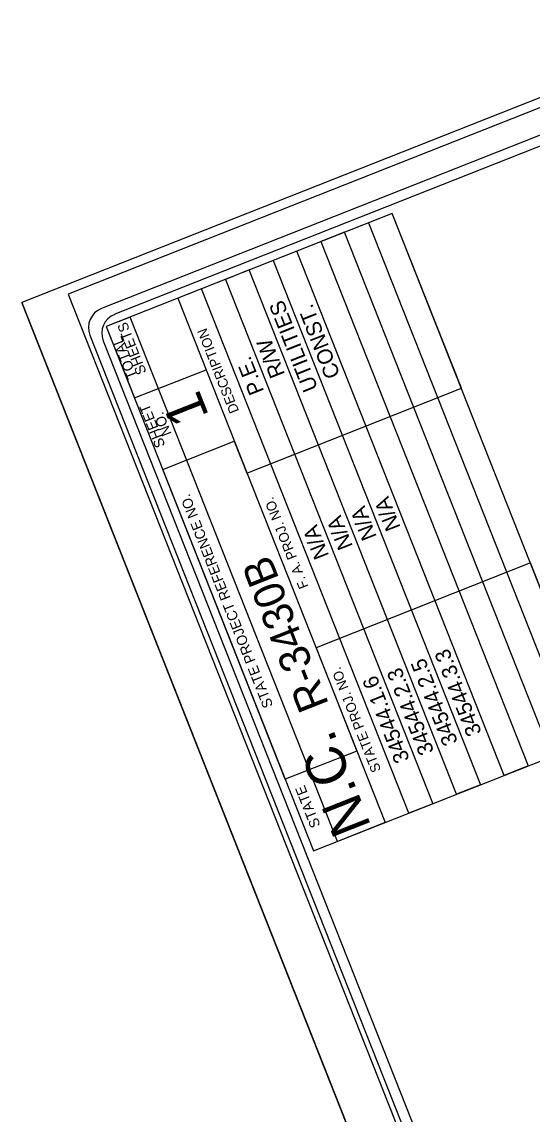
# Model space of a CAD drawing. Extents: x 1247235 to 1260080, y 742320 to 754020.
# Drawn here: x 1247235 to 1248355, y 748232 to 750629 of the extents above; entities that cross this region are included whole.
import ezdxf

# ---------------------------------------------------------------- set-up
doc = ezdxf.new("R2010")
doc.units = 0
for name, color, linetype in [('Sheet Cutting Line CELL', 7, 'Continuous'), ('Sheet Data Field CELL', 7, 'Continuous'), ('Sheet Plot Border Inside CELL', 7, 'Continuous'), ('Sheet Plot Border Outside CELL', 7, 'Continuous'), ('Sheet Title CELL', 7, 'Continuous')]:
    doc.layers.add(name, color=color, linetype=linetype)

msp = doc.modelspace()

# ---------------------------------------------------------------- linework, layer by layer
at = {"layer": 'Sheet Cutting Line CELL'}
msp.add_line((1250021.3, 742966), (1247234.8, 750013.1), dxfattribs=at)
at = {"layer": 'Sheet Plot Border Inside CELL'}
msp.add_lwpolyline([(1254509, 744803.4), (1251751.5, 751777.2), (1247336.2, 750031.4), (1250093.7, 743057.5)], close=True, dxfattribs=at)
at = {"layer": 'Sheet Plot Border Outside CELL'}
msp.add_lwpolyline([(1247234.8, 750013.1), (1250021.3, 742966), (1254624.4, 744786.1), (1251837.9, 751833.2)], close=True, dxfattribs=at)
at = {"layer": 'Sheet Title CELL'}
for points in [[(1251719.6, 751704.2), (1247409.4, 749999.8)], [(1250932.8, 751368.8), (1247438.6, 749987.2)], [(1248398.2, 749016.5), (1247943.2, 750167.3), (1247890.9, 750146.7), (1248345.9, 748995.9), (1248293.5, 748975.2), (1247838.5, 750126), (1247786.2, 750105.3), (1248241.2, 748954.5), (1248189, 748933.8), (1247733.9, 750084.6), (1247681.6, 750063.9), (1248136.7, 748913.1), (1248084.3, 748892.4), (1247629.3, 750043.2), (1247576.9, 750022.5), (1248032, 748871.7), (1247927.4, 748830.4), (1247472.3, 749981.2), (1247420, 749960.5), (1247875.1, 748809.7), (1248502.8, 749057.9), (1248351.2, 749441.4), (1247880.4, 749255.3), (1247970, 749028.7), (1247813, 748966.6), (1247544.1, 749646.7), (1247701, 749708.7), (1247728.7, 749638.8), (1248199.5, 749825), (1248047.7, 750208.7), (1247420, 749960.5), (1247482.1, 749803.6), (1247639, 749865.7)], [(1248502.8, 749057.9), (1248047.7, 750208.7), (1247995.5, 750188), (1248450.5, 749037.2)], [(1247384.1, 749941.4), (1249832.9, 743748)], [(1247413.3, 749928.8), (1249762.9, 743986.5)]]:
    msp.add_lwpolyline(points, dxfattribs=at)
for centre, end in [((1247425.9, 749958), 201.5739), ((1247455.1, 749945.3), 201.5743)]:
    msp.add_arc(centre, 45, 111.5743, end, dxfattribs=at)

# ---------------------------------------------------------------- texts
at = {"layer": 'Sheet Data Field CELL'}
for s, height, p in [('UTILITIES', 33.75, (1247885.2, 749824.9)), ('CONST.', 33.75, (1247934.1, 749854.1)), ('R/W', 33.75, (1247812.7, 749855.5)), (' P.E.  ', 33.75, (1247771.5, 749806.7)), ('N/A', 33.75, (1248066.4, 749519.7)), ('N/A', 33.75, (1248014.1, 749499)), ('N/A', 33.75, (1247961.8, 749478.3)), ('N/A', 33.75, (1247909.5, 749457.6)), ('R-3430B   ', 67.5, (1247909.2, 749131.1)), ('34544.3.3', 33.75, (1248244.5, 749069.2)), ('34544.2.5', 33.75, (1248192.2, 749048.4)), ('34544.2.3', 33.75, (1248139.9, 749027.8)), ('34544.1.6', 33.75, (1248086.4, 749010.3))]:
    msp.add_text(s, height=height, rotation=111.5743, dxfattribs=at).set_placement(p)
at = {"layer": 'Sheet Title CELL'}
for s, height, p in [('SHEETS', 22.5, (1247508.8, 749860.1)), ('DESCRIPTION', 21.6, (1247711.8, 749775.1)), ('TOTAL', 22.5, (1247488.5, 749850.4)), ('1', 87.1, (1247646.2, 749763.7)), ('SHEET', 22.5, (1247549.9, 749699.5)), ('NO.', 22.5, (1247563.7, 749725)), ('STATE PROJECT REFERENCE NO.', 22.499, (1247786.6, 749128.4)), ('F. A. PROJ. NO.', 21.6, (1247864.2, 749389.7)), ('STATE PROJ. NO.', 21.6, (1248023.5, 748986.7)), ('N.C.', 87.07, (1248002.1, 748863.5)), ('STATE', 22.5, (1247890.5, 748865.4))]:
    msp.add_text(s, height=height, rotation=111.5743, dxfattribs=at).set_placement(p)

doc.saveas('drawing.dxf')
